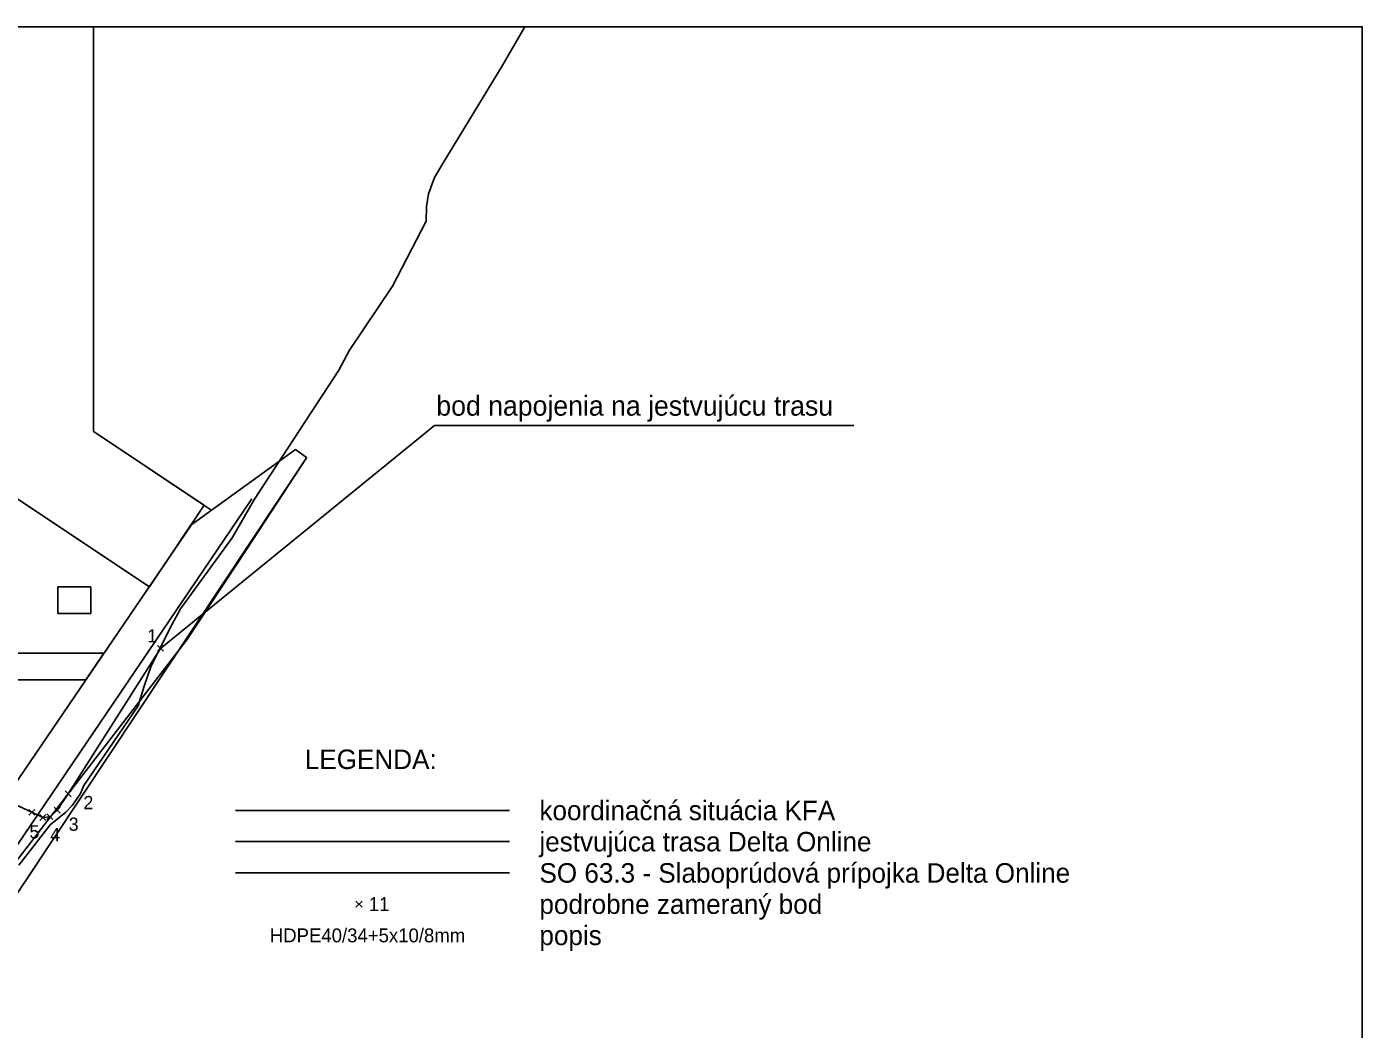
# Model space of a CAD drawing. Extents: x -263995 to -263575, y -1242437 to -1242140.
# Drawn here: x -263776.6 to -263575.4, y -1242291 to -1242140 of the extents above; entities that cross this region are included whole.
import ezdxf

# ---------------------------------------------------------------- set-up
doc = ezdxf.new("R2010")
doc.units = 0
for name, color, linetype in [('DELTA_ONLINE_JESTVUJUCA_TRASA', 7, 'Continuous'), ('KFA_2D_SITUACIA_DSP', 7, 'Continuous'), ('KFA_BODY', 7, 'Continuous'), ('KFA_SO_63-3_PRELOZKA_DELTA_ONLINE_TRASA', 7, 'Continuous'), ('LEGENDA', 7, 'Continuous'), ('POPIS', 7, 'Continuous'), ('RAM_NA_TLAC_A3_1-1000', 7, 'Continuous')]:
    doc.layers.add(name, color=color, linetype=linetype)

msp = doc.modelspace()

# ---------------------------------------------------------------- linework, layer by layer
at = {"layer": 'DELTA_ONLINE_JESTVUJUCA_TRASA'}
for p, q in [((-263705.03, -1242146.04), (-263701.58, -1242140.05)), ((-263713.77, -1242160.39), (-263705.03, -1242146.04)), ((-263715.21, -1242162.77), (-263713.77, -1242160.39)), ((-263716.09, -1242165.2), (-263715.21, -1242162.77)), ((-263716.39, -1242167.09), (-263716.09, -1242165.2)), ((-263716.43, -1242169.34), (-263716.39, -1242167.09)), ((-263721.53, -1242179.12), (-263716.43, -1242169.34)), ((-263727.99, -1242188.77), (-263721.53, -1242179.12)), ((-263729.62, -1242191.75), (-263727.99, -1242188.77)), ((-263742.3, -1242211.17), (-263729.62, -1242191.75)), ((-263745.68, -1242216.98), (-263742.3, -1242211.17)), ((-263753.47, -1242227.7), (-263745.68, -1242216.98)), ((-263754.75, -1242230.12), (-263753.47, -1242227.7)), ((-263757.88, -1242236.29), (-263754.75, -1242230.12)), ((-263758.95, -1242239.35), (-263757.88, -1242236.29)), ((-263759.83, -1242242.28), (-263758.95, -1242239.35)), ((-263768.04, -1242254.28), (-263759.83, -1242242.28)), ((-263769.79, -1242257.33), (-263768.58, -1242255.58)), ((-263768.58, -1242255.58), (-263768.04, -1242254.28)), ((-263770.75, -1242258.31), (-263769.79, -1242257.33)), ((-263773.12, -1242260.22), (-263770.75, -1242258.31)), ((-263777.8, -1242266.3), (-263773.12, -1242260.22))]:
    msp.add_line(p, q, dxfattribs=at)
at = {"layer": 'KFA_2D_SITUACIA_DSP'}
for p, q in [((-263766.58, -1242144.85), (-263766.58, -1242140.05)), ((-263766.58, -1242140.05), (-263766.58, -1242201.01)), ((-263766.58, -1242201.01), (-263766.58, -1242144.85)), ((-263758.42, -1242206.43), (-263766.58, -1242201.01)), ((-263766.58, -1242201.01), (-263749.88, -1242212.11)), ((-263736.13, -1242203.7), (-263751.89, -1242215.1)), ((-263736.13, -1242203.7), (-263734.47, -1242204.91)), ((-263822.88, -1242337.91), (-263734.49, -1242204.94)), ((-263743.42, -1242218.61), (-263734.49, -1242204.94)), ((-263734.49, -1242204.94), (-263734.47, -1242204.91)), ((-263734.47, -1242204.91), (-263734.47, -1242204.91)), ((-263757.19, -1242207.25), (-263758.42, -1242206.43)), ((-263748.89, -1242212.77), (-263757.19, -1242207.25)), ((-263758.15, -1242224.37), (-263781.36, -1242208.94)), ((-263794.9, -1242288.03), (-263742.74, -1242211.14)), ((-263749.88, -1242212.11), (-263758.15, -1242224.37)), ((-263798.9, -1242284.13), (-263751.86, -1242215.08)), ((-263751.89, -1242215.1), (-263751.89, -1242215.1)), ((-263743.42, -1242218.61), (-263752.52, -1242232.37)), ((-263771.97, -1242224.38), (-263766.97, -1242224.38)), ((-263771.97, -1242228.38), (-263771.97, -1242224.38)), ((-263766.97, -1242224.38), (-263766.97, -1242228.38)), ((-263766.97, -1242228.38), (-263771.97, -1242228.38)), ((-263752.52, -1242232.37), (-263782.17, -1242270.82)), ((-263781.97, -1242234.38), (-263771.97, -1242234.38)), ((-263771.97, -1242234.38), (-263765.01, -1242234.38)), ((-263765.01, -1242234.38), (-263767.74, -1242238.38)), ((-263771.97, -1242238.38), (-263781.97, -1242238.38)), ((-263767.74, -1242238.38), (-263771.97, -1242238.38))]:
    msp.add_line(p, q, dxfattribs=at)
at = {"layer": 'KFA_BODY'}
for p, q in [((-263756.92, -1242234.09), (-263756.04, -1242233.21)), ((-263756.04, -1242234.09), (-263756.92, -1242233.21)), ((-263770.82, -1242255.99), (-263769.94, -1242255.11)), ((-263769.94, -1242255.99), (-263770.82, -1242255.11)), ((-263776.31, -1242258.77), (-263775.42, -1242257.89)), ((-263775.42, -1242258.77), (-263776.31, -1242257.89)), ((-263772.5, -1242258.46), (-263771.61, -1242257.57)), ((-263771.61, -1242258.46), (-263772.5, -1242257.57)), ((-263774.66, -1242259.55), (-263773.77, -1242258.67)), ((-263773.77, -1242259.55), (-263774.66, -1242258.67)), ((-263773.59, -1242259.43), (-263772.71, -1242258.55)), ((-263772.71, -1242259.43), (-263773.59, -1242258.55))]:
    msp.add_line(p, q, dxfattribs=at)
at = {"layer": 'KFA_SO_63-3_PRELOZKA_DELTA_ONLINE_TRASA'}
msp.add_line((-263770.38, -1242255.55), (-263770.38, -1242255.55), dxfattribs=at)
for points in [[(-263756.48, -1242233.65), (-263770.38, -1242255.55)], [(-263770.38, -1242255.55), (-263772.06, -1242258.02), (-263773.15, -1242258.99), (-263774.21, -1242259.11), (-263775.87, -1242258.33), (-263786.99, -1242253.25)]]:
    msp.add_lwpolyline(points, dxfattribs=at)
at = {"layer": 'LEGENDA'}
for p, q in [((-263745.16, -1242258.05), (-263703.9, -1242258.05)), ((-263745.16, -1242262.75), (-263703.9, -1242262.75)), ((-263745.16, -1242267.46), (-263703.9, -1242267.46)), ((-263727.03, -1242272.62), (-263726.11, -1242271.7)), ((-263726.11, -1242272.62), (-263727.03, -1242271.7))]:
    msp.add_line(p, q, dxfattribs=at)
at = {"layer": 'POPIS'}
for p, q in [((-263756.48, -1242233.65), (-263715.21, -1242200.09)), ((-263715.21, -1242200.09), (-263652, -1242200.09))]:
    msp.add_line(p, q, dxfattribs=at)
at = {"layer": 'RAM_NA_TLAC_A3_1-1000'}
msp.add_lwpolyline([(-263995.41, -1242140.05), (-263575.41, -1242140.05), (-263575.41, -1242437.05), (-263995.41, -1242437.05)], close=True, dxfattribs=at)

# ---------------------------------------------------------------- texts
at = {"layer": 'KFA_BODY'}
for s, p in [('1', (-263758.46, -1242232.76)), ('2', (-263768.09, -1242257.87)), ('3', (-263770.31, -1242261.12)), ('5', (-263776.22, -1242262.27)), ('4', (-263773.09, -1242262.68))]:
    msp.add_text(s, height=2, dxfattribs=at).set_placement(p)
at = {"layer": 'LEGENDA'}
for s, height, p in [('LEGENDA:', 2.939, (-263734.74, -1242251.82)), ('koordinačná situácia KFA', 2.9391, (-263699.39, -1242259.52)), ('jestvujúca trasa Delta Online', 2.9391, (-263699.39, -1242264.22)), ('SO 63.3 - Slaboprúdová prípojka Delta Online', 2.9391, (-263699.39, -1242268.93)), ('11', 2.09, (-263725.1, -1242273.2)), ('podrobne zameraný bod', 2.9391, (-263699.39, -1242273.63)), ('HDPE40/34+5x10/8mm', 2.09, (-263740.01, -1242277.91)), ('popis', 2.939, (-263699.39, -1242278.33))]:
    msp.add_text(s, height=height, dxfattribs=at).set_placement(p)
at = {"layer": 'POPIS'}
msp.add_text('bod napojenia na jestvujúcu trasu', height=3, dxfattribs=at).set_placement((-263714.92, -1242198.61))

doc.saveas('drawing.dxf')
